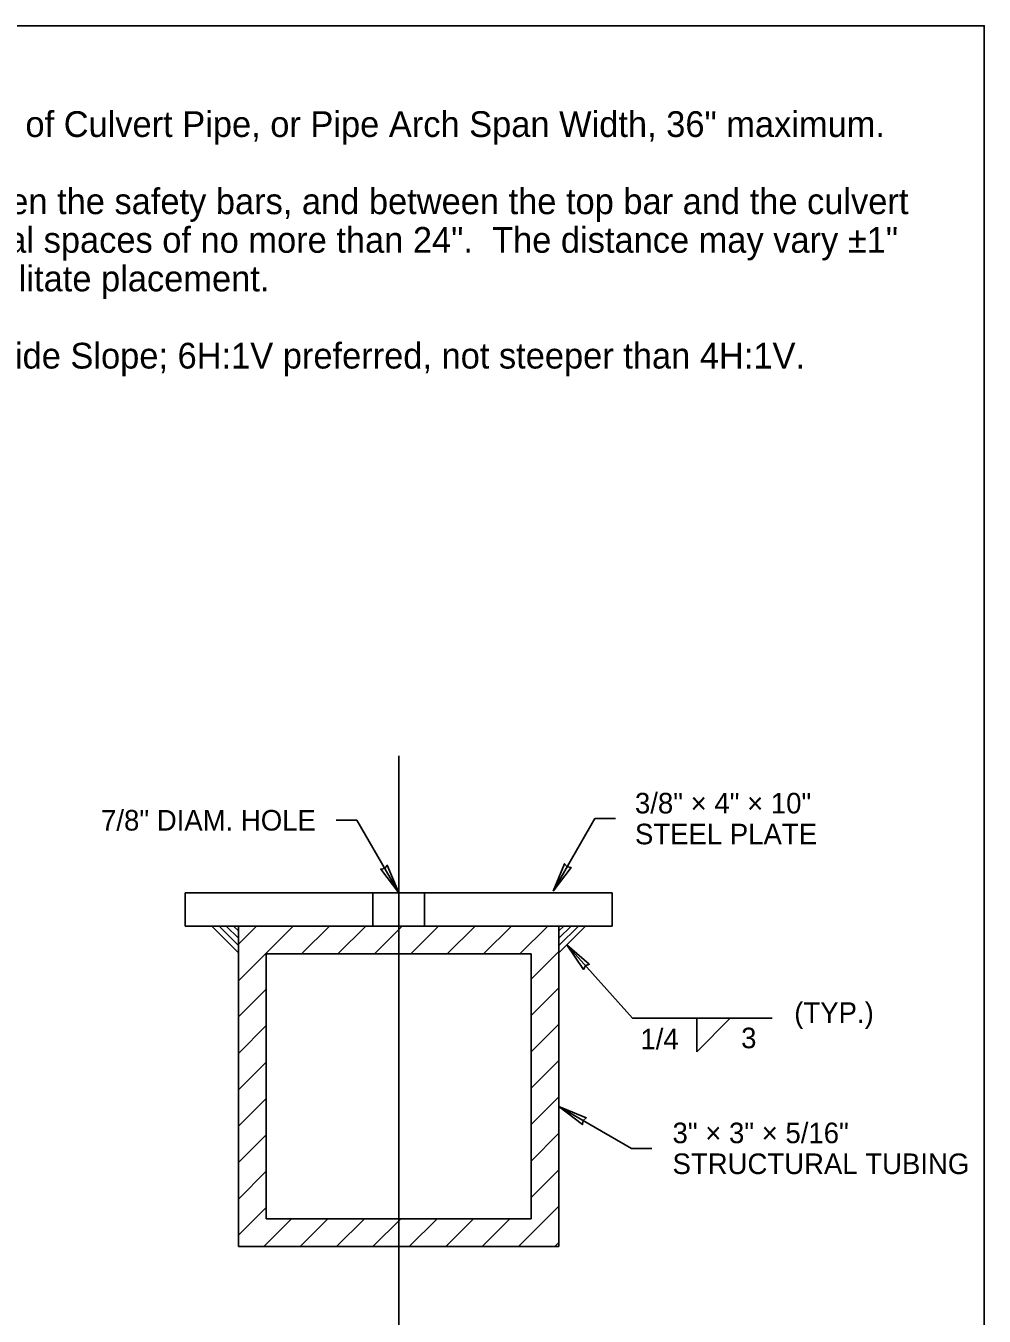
# Model space of a CAD drawing. Extents: x 99862 to 103151, y 100000 to 102076.
# Drawn here: x 102406 to 103151, y 101073 to 102076 of the extents above; entities that cross this region are included whole.
import ezdxf

# ---------------------------------------------------------------- set-up
doc = ezdxf.new("R2010")
doc.units = 0
for name, color, linetype in [('Level 1', 7, 'Continuous'), ('Level 15', 7, 'Continuous'), ('Level 2', 7, 'Continuous'), ('Level 20', 7, 'Continuous'), ('Level 22', 7, 'Continuous'), ('Level 36', 7, 'Continuous'), ('Level 60', 7, 'Continuous')]:
    doc.layers.add(name, color=color, linetype=linetype)

msp = doc.modelspace()

# ---------------------------------------------------------------- linework, layer by layer
at = {"layer": 'Level 1'}
for p, q in [((102530, 101401.7), (102530, 101375.8)), ((102530, 101401.7), (102862, 101401.7)), ((102862, 101401.7), (102862, 101375.8)), ((102530, 101375.8), (102862, 101375.8)), ((102571.4, 101126.7), (102571.4, 101375.8)), ((102571.4, 101375.8), (102820.5, 101375.8)), ((102820.5, 101126.7), (102820.5, 101375.8)), ((102593.1, 101354.1), (102798.9, 101354.1)), ((102593.1, 101148.3), (102593.1, 101354.1)), ((102798.9, 101148.3), (102798.9, 101354.1)), ((102593.1, 101148.3), (102798.9, 101148.3)), ((102571.4, 101126.7), (102820.5, 101126.7))]:
    msp.add_line(p, q, dxfattribs=at)
msp.add_lwpolyline([(99862, 99999.5), (103151, 99999.5), (103151, 102075.5), (99862, 102075.5)], close=True, dxfattribs=at)
at = {"layer": 'Level 15'}
for p, q in [((102696, 101508.2), (102696, 101060.5)), ((102647.5, 101458), (102663.5, 101458)), ((102696, 101401.7), (102663.5, 101458)), ((102816, 101403), (102848.5, 101459.3)), ((102848.5, 101459.3), (102864.5, 101459.3)), ((102877.7, 101304.1), (102826.6, 101361.1)), ((102877.7, 101304.1), (102986.2, 101304.1)), ((102927.6, 101278.1), (102927.6, 101304.1)), ((102927.6, 101278.1), (102953.6, 101304.1)), ((102820.5, 101235.5), (102876.8, 101203)), ((102876.8, 101203), (102892.8, 101203))]:
    msp.add_line(p, q, dxfattribs=at)
for points in [[(102696, 101401.7), (102687.1, 101423), (102685.1, 101420.6), (102682, 101420)], [(102816, 101403), (102830, 101421.3), (102826.9, 101421.8), (102824.8, 101424.2)], [(102826.6, 101361.1), (102844.1, 101346.1), (102841.1, 101344.9), (102839.6, 101342.1)], [(102820.5, 101235.5), (102841.8, 101226.6), (102839.3, 101224.6), (102838.8, 101221.5)]]:
    msp.add_lwpolyline(points, close=True, dxfattribs=at)
at = {"layer": 'Level 2'}
for p, q in [((102571.4, 101375.8), (102571.4, 101375.8)), ((102571.4, 101361.6), (102585.6, 101375.8)), ((102571.4, 101333.3), (102613.9, 101375.8)), ((102620.5, 101354.1), (102642.1, 101375.8)), ((102648.8, 101354.1), (102670.4, 101375.8)), ((102677.1, 101354.1), (102698.7, 101375.8)), ((102705.4, 101354.1), (102727, 101375.8)), ((102733.7, 101354.1), (102755.3, 101375.8)), ((102761.9, 101354.1), (102783.6, 101375.8)), ((102790.2, 101354.1), (102811.8, 101375.8)), ((102798.9, 101334.5), (102820.5, 101356.1)), ((102571.4, 101305.1), (102593.1, 101326.7)), ((102798.9, 101306.2), (102820.5, 101327.8)), ((102571.4, 101276.8), (102593.1, 101298.4)), ((102798.9, 101277.9), (102820.5, 101299.6)), ((102571.4, 101248.5), (102593.1, 101270.1)), ((102798.9, 101249.7), (102820.5, 101271.3)), ((102571.4, 101220.2), (102593.1, 101241.8)), ((102798.9, 101221.4), (102820.5, 101243)), ((102571.4, 101191.9), (102593.1, 101213.6)), ((102798.9, 101193.1), (102820.5, 101214.7)), ((102571.4, 101163.6), (102593.1, 101185.3)), ((102798.9, 101164.8), (102820.5, 101186.4)), ((102571.4, 101135.4), (102593.1, 101157)), ((102789.1, 101126.7), (102820.5, 101158.1)), ((102591.1, 101126.7), (102612.7, 101148.3)), ((102619.4, 101126.7), (102641, 101148.3)), ((102647.6, 101126.7), (102669.3, 101148.3)), ((102675.9, 101126.7), (102697.6, 101148.3)), ((102704.2, 101126.7), (102725.8, 101148.3)), ((102732.5, 101126.7), (102754.1, 101148.3)), ((102760.8, 101126.7), (102782.4, 101148.3)), ((102817.3, 101126.7), (102820.5, 101129.9))]:
    msp.add_line(p, q, dxfattribs=at)
at = {"layer": 'Level 22'}
for p, q in [((102550.7, 101375.8), (102571.4, 101355)), ((102556.4, 101375.8), (102571.4, 101360.7)), ((102562, 101375.8), (102571.4, 101366.4)), ((102567.7, 101375.8), (102571.4, 101372)), ((102841.2, 101375.8), (102820.5, 101355)), ((102835.6, 101375.8), (102820.5, 101360.7)), ((102829.9, 101375.8), (102820.5, 101366.4)), ((102824.3, 101375.8), (102820.5, 101372))]:
    msp.add_line(p, q, dxfattribs=at)
at = {"layer": 'Level 36'}
for p, q in [((102676, 101401.7), (102676, 101375.8)), ((102716, 101401.7), (102716, 101375.8))]:
    msp.add_line(p, q, dxfattribs=at)
at = {"layer": 'Level 60'}
msp.add_line((103151, 102075.5), (103151, 102075.5), dxfattribs=at)

# ---------------------------------------------------------------- texts
at = {"layer": 'Level 20'}
for s, height, p in [('D = Inside Diameter of Culvert Pipe, or Pipe Arch Span Width, 36" maximum.', 20, (102161.4, 101989.1)), ('The distance between the safety bars, and between the top bar and the culvert', 20, (102161.4, 101929.1)), ('crown, shall be equal spaces of no more than 24".  The distance may vary ±1"', 20, (102161.4, 101899.1)), ('between bars to facilitate placement.', 20, (102161.4, 101869.1)), ('Slope shall match Side Slope; 6H:1V preferred, not steeper than 4H:1V.', 20, (102161.4, 101809.1)), ('3/8" × 4" × 10"', 16, (102879.6, 101463.3)), ('7/8" DIAM. HOLE', 16, (102464.7, 101450)), ('STEEL PLATE', 16, (102879.6, 101439.3)), ('(TYP.)', 16, (103003.4, 101300.5)), (' 1/4 ', 16, (102877.9, 101279.9)), ('3', 16, (102962.1, 101280.8)), ('3" × 3" × 5/16"', 16, (102908.8, 101207)), ('STRUCTURAL TUBING', 16, (102908.8, 101183))]:
    msp.add_text(s, height=height, dxfattribs=at).set_placement(p)

doc.saveas('drawing.dxf')
